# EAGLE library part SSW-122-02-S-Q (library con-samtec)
THROUGH-HOLE .025" SQ POST SOCKET Source: Samtec SSW.pdf
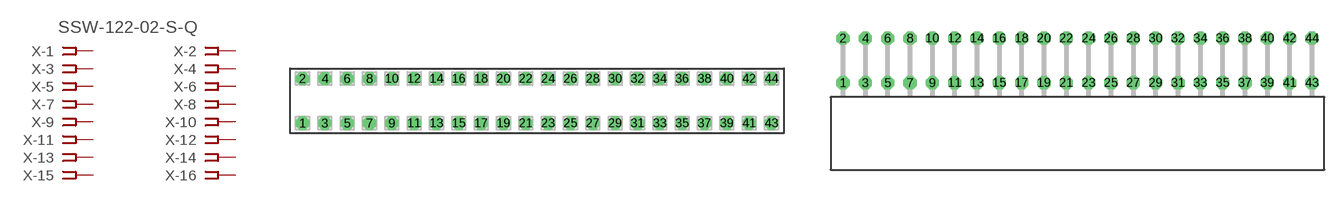
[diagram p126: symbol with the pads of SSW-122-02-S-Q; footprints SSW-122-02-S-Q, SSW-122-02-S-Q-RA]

Designator prefix X; gates -1=FPINV -2=FPIN -3=FPIN -4=FPIN -5=FPIN -6=FPIN -7=FPIN -8=FPIN -9=FPIN -10=FPIN -11=FPIN -12=FPIN -13=FPIN -14=FPIN -15=FPIN -16=FPIN -17=FPIN -18=FPIN -19=FPIN -20=FPIN -21=FPIN -22=FPIN -23=FPIN -24=FPIN -25=FPIN -26=FPIN -27=FPIN -28=FPIN -29=FPIN -30=FPIN -31=FPIN -32=FPIN -33=FPIN -34=FPIN -35=FPIN -36=FPIN -37=FPIN -38=FPIN -39=FPIN -40=FPIN -41=FPIN -42=FPIN -43=FPIN -44=FPIN

## SSW-122-02-S-Q (MPN: SSW-122-02-S-Q; OC_FARNELL: unknown; OC_NEWARK: 82P8752)  [SSW-122-02-S-Q]
1  -1:1  pas
2  -2:1  pas
3  -3:1  pas
4  -4:1  pas
5  -5:1  pas
6  -6:1  pas
7  -7:1  pas
8  -8:1  pas
9  -9:1  pas
10  -10:1  pas
11  -11:1  pas
12  -12:1  pas
13  -13:1  pas
14  -14:1  pas
15  -15:1  pas
16  -16:1  pas
17  -17:1  pas
18  -18:1  pas
19  -19:1  pas
20  -20:1  pas
21  -21:1  pas
22  -22:1  pas
23  -23:1  pas
24  -24:1  pas
25  -25:1  pas
26  -26:1  pas
27  -27:1  pas
28  -28:1  pas
29  -29:1  pas
30  -30:1  pas
31  -31:1  pas
32  -32:1  pas
33  -33:1  pas
34  -34:1  pas
35  -35:1  pas
36  -36:1  pas
37  -37:1  pas
38  -38:1  pas
39  -39:1  pas
40  -40:1  pas
41  -41:1  pas
42  -42:1  pas
43  -43:1  pas
44  -44:1  pas

## SSW-122-02-S-QRA (MPN: SSW-122-02-S-Q-RA; OC_FARNELL: unknown; OC_NEWARK: 82P8753)  [SSW-122-02-S-Q-RA]
Pads as for SSW-122-02-S-Q

## Footprint SSW-122-02-S-Q (pad centres in mm)
THROUGH-HOLE .025" SQ POST SOCKET Source: Samtec SSW.pdf
drill 1 pad 1.5 octagon: 1 -26.67,-2.54; 2 -26.67,2.54; 3 -24.13,-2.54; 4 -24.13,2.54; 5 -21.59,-2.54; 6 -21.59,2.54; 7 -19.05,-2.54; 8 -19.05,2.54; 9 -16.51,-2.54; 10 -16.51,2.54; 11 -13.97,-2.54; 12 -13.97,2.54; 13 -11.43,-2.54; 14 -11.43,2.54; 15 -8.89,-2.54; 16 -8.89,2.54; 17 -6.35,-2.54; 18 -6.35,2.54; 19 -3.81,-2.54; 20 -3.81,2.54; 21 -1.27,-2.54; 22 -1.27,2.54; 23 1.27,-2.54; 24 1.27,2.54; 25 3.81,-2.54; 26 3.81,2.54; 27 6.35,-2.54; 28 6.35,2.54; 29 8.89,-2.54; 30 8.89,2.54; 31 11.43,-2.54; 32 11.43,2.54; 33 13.97,-2.54; 34 13.97,2.54; 35 16.51,-2.54; 36 16.51,2.54; 37 19.05,-2.54; 38 19.05,2.54; 39 21.59,-2.54; 40 21.59,2.54; 41 24.13,-2.54; 42 24.13,2.54; 43 26.67,-2.54; 44 26.67,2.54

## Footprint SSW-122-02-S-Q-RA (pad centres in mm)
THROUGH-HOLE .025" SQ POST SOCKET Source: Samtec SSW.pdf
drill 1 pad 1.5 octagon: 1 -26.67,1.524; 2 -26.67,6.604; 3 -24.13,1.524; 4 -24.13,6.604; 5 -21.59,1.524; 6 -21.59,6.604; 7 -19.05,1.524; 8 -19.05,6.604; 9 -16.51,1.524; 10 -16.51,6.604; 11 -13.97,1.524; 12 -13.97,6.604; 13 -11.43,1.524; 14 -11.43,6.604; 15 -8.89,1.524; 16 -8.89,6.604; 17 -6.35,1.524; 18 -6.35,6.604; 19 -3.81,1.524; 20 -3.81,6.604; 21 -1.27,1.524; 22 -1.27,6.604; 23 1.27,1.524; 24 1.27,6.604; 25 3.81,1.524; 26 3.81,6.604; 27 6.35,1.524; 28 6.35,6.604; 29 8.89,1.524; 30 8.89,6.604; 31 11.43,1.524; 32 11.43,6.604; 33 13.97,1.524; 34 13.97,6.604; 35 16.51,1.524; 36 16.51,6.604; 37 19.05,1.524; 38 19.05,6.604; 39 21.59,1.524; 40 21.59,6.604; 41 24.13,1.524; 42 24.13,6.604; 43 26.67,1.524; 44 26.67,6.604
